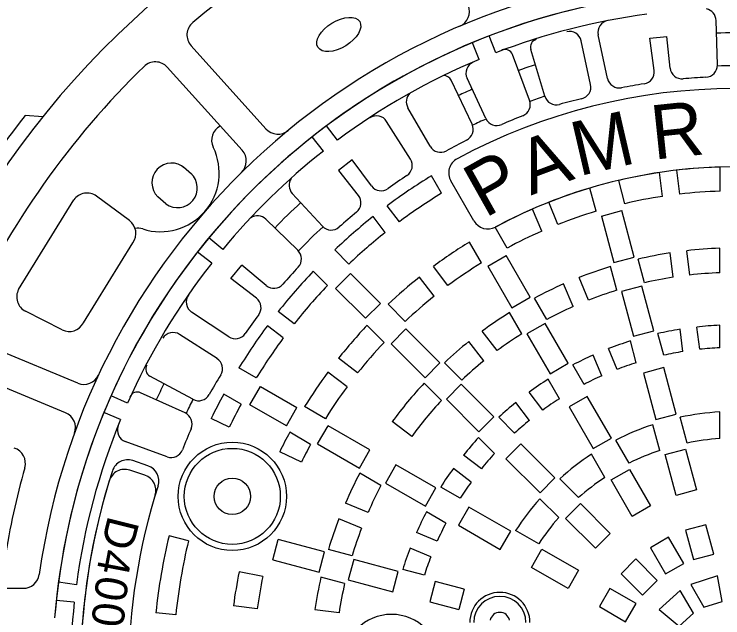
# Model space of a CAD drawing. Extents: x -7.1 to 10, y -5 to 6.
# Drawn here: x -5.508 to -4.588, y 0.793 to 1.576 of the extents above; entities that cross this region are included whole.
import ezdxf

# ---------------------------------------------------------------- set-up
doc = ezdxf.new("R2010")
doc.units = 0
doc.layers.add('Level 1', color=7, linetype='Continuous')

# ---------------------------------------------------------------- blocks, each defined once
blk = doc.blocks.new('CRAN')
at = {"layer": 'Level 1'}
for p, q in [((-3.652, 6.599), (-1.391, 7.083)), ((-3.232, 4.178), (-1.568, 4.4)), ((-1.568, 4.4), (-1.47, 3.52)), ((-3.114, 3.352), (-1.47, 3.52)), ((-2.949, 0.9), (-0.638, 0.965)), ((-2.949, -0.892), (-0.638, -0.957)), ((-3.114, -3.345), (-1.471, -3.52)), ((-1.568, -4.392), (-1.47, -3.512)), ((-3.232, -4.17), (-1.568, -4.392)), ((-3.652, -6.592), (-1.391, -7.076))]:
    blk.add_line(p, q, dxfattribs=at)
for centre, radius, start, end in [((-1.26, 6.472), 0.625, 11.0144, 102.0722), ((-3.521, 5.988), 0.625, 102.0722, 190.9368), ((-34.491, 0.004), 30.918, 8.7409, 10.9368), ((-3.315, 4.797), 0.625, 188.7409, 277.6056), ((-3.048, 2.731), 0.625, 96.0776, 184.9422), ((-34.473, 0.013), 30.918, 2.7463, 4.9422), ((-2.967, 1.524), 0.625, 182.7463, 271.611), ((-0.656, 1.589), 0.625, 271.611, 348.8242), ((-2.967, -1.517), 0.625, 88.389, 177.2537), ((-0.656, -1.582), 0.625, 11.1758, 88.389), ((-34.473, -0.006), 30.918, 355.0578, 357.2537), ((-3.048, -2.723), 0.625, 175.0578, 263.9224), ((-3.315, -4.79), 0.625, 82.3944, 171.2591), ((-34.491, 0.004), 30.918, 349.0632, 351.2591), ((-3.521, -5.981), 0.625, 169.0632, 257.9278), ((-1.26, -6.464), 0.625, 257.9278, 348.9856)]:
    blk.add_arc(centre, radius, start, end, dxfattribs=at)

msp = doc.modelspace()

# ---------------------------------------------------------------- linework, layer by layer
at = {"layer": 'Level 1'}
for p, q in [((-4.59489, 1.51031), (-4.59652, 1.56809)), ((-4.88249, 1.52608), (-4.89092, 1.54795)), ((-4.73738, 1.49275), (-4.74947, 1.54927)), ((-4.68239, 1.54485), (-4.66039, 1.5473)), ((-4.6562, 1.50619), (-4.66058, 1.54728)), ((-4.90382, 1.51753), (-4.91283, 1.53917)), ((-4.75936, 1.48502), (-4.77158, 1.54152)), ((-4.67684, 1.50325), (-4.68239, 1.54485)), ((-5.18073, 1.42741), (-5.27802, 1.53531)), ((-4.81886, 1.4697), (-4.83705, 1.53039)), ((-4.83861, 1.4644), (-4.86087, 1.52372)), ((-5.21167, 1.39951), (-5.30897, 1.50741)), ((-4.91326, 1.43331), (-4.94052, 1.49051)), ((-4.89526, 1.44059), (-4.91972, 1.49296)), ((-4.96766, 1.40474), (-4.99651, 1.45483)), ((-5.47019, 1.44311), (-5.49337, 1.44454)), ((-5.08805, 1.41258), (-5.10206, 1.43136)), ((-5.10628, 1.39859), (-5.12079, 1.417)), ((-5.2774, 1.36875), (-5.28788, 1.3778)), ((-4.666, 1.33974), (-4.67008, 1.37073)), ((-4.64355, 1.34273), (-4.64752, 1.37372)), ((-4.59125, 1.3465), (-4.59118, 1.37776)), ((-4.95299, 1.3438), (-4.96596, 1.36639)), ((-4.91087, 1.30787), (-4.94083, 1.35976)), ((-4.71515, 1.33028), (-4.72295, 1.36055)), ((-4.7523, 1.32035), (-4.76032, 1.35057)), ((-5.50187, 1.21905), (-5.43013, 1.33531)), ((-5.35803, 1.30832), (-5.40074, 1.33998)), ((-5.3107, 1.33021), (-5.32118, 1.33927)), ((-5.00763, 1.30688), (-5.02341, 1.32759)), ((-4.80184, 1.30318), (-4.8137, 1.33209)), ((-4.82275, 1.29449), (-4.83472, 1.32336)), ((-4.7454, 1.31425), (-4.71899, 1.32133)), ((-4.70281, 1.26094), (-4.71899, 1.32133)), ((-4.70281, 1.26094), (-4.71899, 1.32133)), ((-5.02588, 1.29284), (-5.04174, 1.31351)), ((-4.7454, 1.31425), (-4.72922, 1.25386)), ((-4.86778, 1.27262), (-4.88315, 1.29984)), ((-5.4177, 1.17549), (-5.35344, 1.27954)), ((-5.23683, 1.27101), (-5.25489, 1.28595)), ((-4.9011, 1.25342), (-4.91667, 1.28053)), ((-5.07326, 1.25179), (-5.09151, 1.27038)), ((-4.59178, 1.24061), (-4.59178, 1.2724)), ((-5.25124, 1.25311), (-5.26969, 1.26756)), ((-4.89285, 1.24931), (-4.86917, 1.26298)), ((-4.83791, 1.20884), (-4.86917, 1.26298)), ((-4.83791, 1.20884), (-4.86917, 1.26298)), ((-4.72922, 1.25386), (-4.70281, 1.26094)), ((-4.65216, 1.23482), (-4.65631, 1.26633)), ((-4.63048, 1.23772), (-4.63462, 1.26923)), ((-4.68948, 1.22762), (-4.69764, 1.25834)), ((-5.10101, 1.22412), (-5.11939, 1.24259)), ((-4.9445, 1.22401), (-4.96344, 1.24887)), ((-4.89285, 1.24931), (-4.86159, 1.19517)), ((-4.7254, 1.21794), (-4.73363, 1.24865)), ((-5.0903, 1.22025), (-5.07096, 1.23959)), ((-5.07096, 1.23959), (-5.03229, 1.20091)), ((-4.96245, 1.2102), (-4.98148, 1.23499)), ((-4.76204, 1.20513), (-4.7742, 1.23449)), ((-4.78223, 1.19672), (-4.79439, 1.22608)), ((-5.05162, 1.18157), (-5.0903, 1.22025)), ((-4.69269, 1.2232), (-4.7191, 1.21612)), ((-4.7191, 1.21612), (-4.7036, 1.15824)), ((-4.67718, 1.16532), (-4.69269, 1.2232)), ((-4.86159, 1.19517), (-4.83791, 1.20884)), ((-4.81641, 1.1801), (-4.83225, 1.20767)), ((-5.05162, 1.18157), (-5.03229, 1.20091)), ((-5.00028, 1.17743), (-5.02218, 1.19974)), ((-5.44549, 1.1667), (-5.49288, 1.19069)), ((-5.14423, 1.17432), (-5.16484, 1.19025)), ((-4.84861, 1.16146), (-4.86451, 1.18899)), ((-5.15824, 1.15604), (-5.1789, 1.17189)), ((-5.0275, 1.15025), (-5.04956, 1.17241)), ((-4.81837, 1.175), (-4.84205, 1.16133)), ((-4.78841, 1.12311), (-4.81837, 1.175)), ((-4.61779, 1.14132), (-4.62158, 1.17018)), ((-4.59178, 1.14332), (-4.59178, 1.17244)), ((-5.24432, 1.12934), (-5.29292, 1.16064)), ((-5.01847, 1.14842), (-4.99913, 1.16776)), ((-4.95493, 1.12355), (-4.99913, 1.16776)), ((-4.95493, 1.12355), (-4.99913, 1.16776)), ((-4.88068, 1.13961), (-4.90002, 1.16482)), ((-4.84205, 1.16133), (-4.81209, 1.10944)), ((-4.7036, 1.15824), (-4.67718, 1.16532)), ((-4.66449, 1.13361), (-4.67197, 1.16175)), ((-4.63947, 1.13841), (-4.64327, 1.16727)), ((-5.425, 1.09741), (-5.55924, 1.15302)), ((-4.89801, 1.12625), (-4.91735, 1.15146)), ((-4.70022, 1.12396), (-4.70776, 1.1521)), ((-5.01847, 1.14842), (-4.97426, 1.10421)), ((-4.72483, 1.1153), (-4.73597, 1.14219)), ((-4.74502, 1.10688), (-4.75616, 1.13377)), ((-5.06181, 1.11061), (-5.08654, 1.12972)), ((-4.97426, 1.10421), (-4.95493, 1.12355)), ((-4.92672, 1.10136), (-4.94915, 1.12388)), ((-4.81209, 1.10944), (-4.78841, 1.12311)), ((-5.44094, 1.05892), (-5.57519, 1.11453)), ((-5.19338, 1.10412), (-5.21581, 1.11735)), ((-4.76795, 1.09576), (-4.78246, 1.12101)), ((-4.66437, 1.1175), (-4.69078, 1.11042)), ((-4.64818, 1.05709), (-4.66437, 1.1175)), ((-5.27556, 1.07643), (-5.33134, 1.10649)), ((-5.07558, 1.09263), (-5.10038, 1.11165)), ((-4.69078, 1.11042), (-4.6746, 1.05001)), ((-4.953, 1.07501), (-4.97548, 1.09749)), ((-4.9273, 1.09592), (-4.94663, 1.07658)), ((-4.88493, 1.05355), (-4.9273, 1.09592)), ((-4.79996, 1.0772), (-4.81453, 1.10242)), ((-5.20167, 1.06925), (-5.188, 1.09293)), ((-5.188, 1.09293), (-5.14063, 1.06558)), ((-4.82149, 1.06246), (-4.83921, 1.08556)), ((-5.36042, 1.0713), (-5.38185, 1.08081)), ((-5.28578, 1.05871), (-5.34347, 1.08492)), ((-5.21302, 1.07021), (-5.23555, 1.0833)), ((-4.94663, 1.07658), (-4.90426, 1.03421)), ((-4.76366, 1.08024), (-4.78734, 1.06656)), ((-4.73239, 1.02607), (-4.76366, 1.08024)), ((-5.1543, 1.0419), (-5.20167, 1.06925)), ((-5.10364, 1.05118), (-5.13056, 1.06706)), ((-4.83881, 1.0491), (-4.85653, 1.0722)), ((-5.36946, 1.05017), (-5.39113, 1.0591)), ((-5.1543, 1.0419), (-5.14063, 1.06558)), ((-4.78734, 1.06656), (-4.75607, 1.0124)), ((-4.59178, 1.02541), (-4.59178, 1.06001)), ((-5.22843, 1.04026), (-5.25185, 1.05164)), ((-4.90426, 1.03421), (-4.88493, 1.05355)), ((-4.85808, 1.03243), (-4.87863, 1.05307)), ((-4.6746, 1.05001), (-4.64818, 1.05709)), ((-4.63422, 1.01969), (-4.6431, 1.05312)), ((-5.1137, 1.01846), (-5.10002, 1.04214)), ((-5.04588, 1.01088), (-5.10002, 1.04214)), ((-5.04588, 1.01088), (-5.10002, 1.04214)), ((-4.9916, 1.02822), (-5.01681, 1.04757)), ((-4.6697, 1.01007), (-4.67866, 1.04349)), ((-5.12289, 1.01789), (-5.14993, 1.03359)), ((-5.309, 1.00182), (-5.36332, 1.02156)), ((-4.8842, 1.00621), (-4.9048, 1.02681)), ((-4.75607, 1.0124), (-4.73239, 1.02607)), ((-4.70923, 0.99357), (-4.72646, 1.02355)), ((-5.1137, 1.01846), (-5.05955, 0.9872)), ((-4.84992, 1.01854), (-4.86926, 0.99921)), ((-4.8057, 0.97432), (-4.84992, 1.01854)), ((-5.13472, 0.99477), (-5.16283, 1.00841)), ((-5.05955, 0.9872), (-5.04588, 1.01088)), ((-4.90118, 0.98641), (-4.92427, 1.00413)), ((-4.74101, 0.97509), (-4.75831, 1.00505)), ((-4.66245, 1.00469), (-4.63604, 1.01177)), ((-4.64828, 0.9518), (-4.66245, 1.00469)), ((-4.63604, 1.01177), (-4.62187, 0.95888)), ((-5.3339, 0.99027), (-5.35366, 0.99688)), ((-4.86926, 0.99921), (-4.82503, 0.95499)), ((-5.33781, 0.97785), (-5.35757, 0.98446)), ((-5.01204, 0.99134), (-5.02571, 0.96766)), ((-4.96015, 0.96138), (-5.01204, 0.99134)), ((-4.91445, 0.96902), (-4.93755, 0.98674)), ((-4.73261, 0.97177), (-4.70893, 0.98544)), ((-4.70893, 0.98544), (-4.68155, 0.93802)), ((-5.03146, 0.96449), (-5.05899, 0.98039)), ((-5.02571, 0.96766), (-4.97382, 0.9377)), ((-4.82503, 0.95499), (-4.8057, 0.97432)), ((-4.77491, 0.94892), (-4.79931, 0.97342)), ((-4.70523, 0.92435), (-4.73261, 0.97177)), ((-4.97382, 0.9377), (-4.96015, 0.96138)), ((-4.92875, 0.94793), (-4.95394, 0.96254)), ((-4.62187, 0.95888), (-4.64828, 0.9518)), ((-5.0483, 0.92953), (-5.07766, 0.94169)), ((-4.80083, 0.92284), (-4.82529, 0.94731)), ((-4.79186, 0.92181), (-4.77252, 0.94114)), ((-4.77252, 0.94114), (-4.7338, 0.90242)), ((-4.9472, 0.91585), (-4.97242, 0.93041)), ((-4.91728, 0.93663), (-4.93095, 0.91295)), ((-4.86312, 0.90536), (-4.91728, 0.93663)), ((-4.68155, 0.93802), (-4.70523, 0.92435)), ((-5.05663, 0.90931), (-5.08599, 0.92147)), ((-4.75314, 0.88309), (-4.79186, 0.92181)), ((-4.93095, 0.91295), (-4.87679, 0.88168)), ((-4.60971, 0.91351), (-4.63612, 0.90643)), ((-4.59957, 0.87566), (-4.60971, 0.91351)), ((-4.95847, 0.89232), (-4.98536, 0.90346)), ((-4.87679, 0.88168), (-4.86312, 0.90536)), ((-4.8268, 0.88879), (-4.85672, 0.90614)), ((-4.7338, 0.90242), (-4.75314, 0.88309)), ((-4.63612, 0.90643), (-4.62598, 0.86859)), ((-5.28138, 0.89256), (-5.30652, 0.89937)), ((-5.17204, 0.86827), (-5.16496, 0.89468)), ((-5.10458, 0.8785), (-5.16496, 0.89468)), ((-5.10458, 0.8785), (-5.16496, 0.89468)), ((-4.65807, 0.89734), (-4.68175, 0.88367)), ((-4.63848, 0.86341), (-4.65807, 0.89734)), ((-4.96679, 0.87209), (-4.99369, 0.88323)), ((-4.68175, 0.88367), (-4.66216, 0.84974)), ((-5.11165, 0.85209), (-5.10458, 0.8785)), ((-5.06905, 0.87339), (-5.09974, 0.88168)), ((-4.83616, 0.85822), (-4.82248, 0.8819)), ((-4.82248, 0.8819), (-4.77506, 0.85452)), ((-4.62598, 0.86859), (-4.59957, 0.87566)), ((-5.17204, 0.86827), (-5.11165, 0.85209)), ((-5.06683, 0.86839), (-5.07391, 0.84198)), ((-5.00896, 0.85288), (-5.06683, 0.86839)), ((-4.70059, 0.86921), (-4.71993, 0.84988)), ((-4.67289, 0.84151), (-4.70059, 0.86921)), ((-4.97515, 0.84802), (-5.00326, 0.85561)), ((-4.78873, 0.83084), (-4.83616, 0.85822)), ((-4.66216, 0.84974), (-4.63848, 0.86341)), ((-5.18496, 0.84632), (-5.21558, 0.85255)), ((-5.01603, 0.82647), (-5.00896, 0.85288)), ((-4.77506, 0.85452), (-4.78873, 0.83084)), ((-4.71993, 0.84988), (-4.69222, 0.82217)), ((-4.59461, 0.84745), (-4.62941, 0.83598)), ((-4.58874, 0.81411), (-4.59461, 0.84745)), ((-5.42689, 0.83586), (-5.45012, 0.83896)), ((-5.07864, 0.83743), (-5.10935, 0.84566)), ((-5.07391, 0.84198), (-5.01603, 0.82647)), ((-4.96114, 0.84007), (-4.96821, 0.81366)), ((-4.92341, 0.82996), (-4.96114, 0.84007)), ((-4.69222, 0.82217), (-4.67289, 0.84151)), ((-5.56204, 0.83118), (-5.49564, 0.83118)), ((-4.92341, 0.82996), (-4.93048, 0.80355)), ((-4.73439, 0.83103), (-4.74806, 0.80735)), ((-4.70045, 0.81144), (-4.73439, 0.83103)), ((-4.64294, 0.82817), (-4.67027, 0.80377)), ((-4.62597, 0.79878), (-4.64294, 0.82817)), ((-4.62941, 0.83598), (-4.61244, 0.80659)), ((-5.42962, 0.81305), (-5.45293, 0.81553)), ((-4.96821, 0.81366), (-4.93048, 0.80355)), ((-4.71412, 0.78776), (-4.70045, 0.81144)), ((-4.61244, 0.80659), (-4.58874, 0.81411)), ((-5.192, 0.80441), (-5.22298, 0.80854)), ((-5.08586, 0.7993), (-5.11737, 0.80345)), ((-4.74806, 0.80735), (-4.71412, 0.78776)), ((-4.67027, 0.80377), (-4.64433, 0.78201)), ((-5.29779, 0.79681), (-5.32369, 0.79949)), ((-4.64433, 0.78201), (-4.62597, 0.79878))]:
    msp.add_line(p, q, dxfattribs=at)
for radius in [0.07031, 0.06231, 0.02369]:
    msp.add_circle((-5.22444, 0.95048), radius, dxfattribs=at)
for centre, radius, start, end in [((-4.57265, 0.72181), 1.15162, 195.07169, 189.12267), ((-4.5725, 0.7217), 1.09834, 112.86457, 129.82243), ((-4.57249, 0.72178), 0.91146, 12.31851, 171.9696), ((-4.57249, 0.72178), 0.88542, 5.66744, 175.39465), ((-4.57249, 0.72178), 0.88542, 5.66744, 126.73442), ((-4.93742, 1.57968), 0.02083, 293.04383, 21.72806), ((-4.61214, 1.56765), 0.01563, 1.61098, 78.82418), ((-4.57249, 0.72178), 0.86198, 97.60558, 111.07801), ((-5.26255, 1.54926), 0.02083, 129.82243, 222.04), ((-4.73419, 1.55254), 0.01563, 101.01435, 192.07218), ((-4.78686, 1.53821), 0.01562, 12.21206, 103.26989), ((-4.57249, 0.72178), 0.83011, 88.3735, 91.6265), ((-4.82707, 1.53338), 0.01042, 105.96915, 196.67866), ((-4.87063, 1.52006), 0.01042, 20.56861, 111.27812), ((-4.57249, 0.72178), 0.88542, 114.66149, 175.39465), ((-4.57249, 0.7217), 1.09834, 134.21887, 155.28148), ((-5.32444, 1.49346), 0.02083, 42.04, 134.25473), ((-4.57249, 0.72178), 0.86198, 112.60558, 126.73442), ((-4.90556, 1.49957), 0.01562, 113.97738, 205.03521), ((-4.57249, 0.72178), 0.83011, 108.15242, 109.7577), ((-4.61051, 1.50987), 0.01563, 272.74634, 1.61098), ((-4.57249, 0.72178), 0.78745, 88.36809, 91.63191), ((-4.69233, 1.50118), 0.01563, 278.74094, 7.60558), ((-4.64066, 1.50785), 0.01563, 186.07758, 274.94222), ((-4.94992, 1.48603), 0.01042, 25.47558, 93.37664), ((-4.7221, 1.49602), 0.01563, 192.07218, 280.93682), ((-4.57273, 0.72221), 0.77294, 92.74634, 94.94222), ((-4.77463, 1.48172), 0.01562, 283.34742, 12.21206), ((-4.57249, 0.72178), 0.77294, 98.74094, 100.93682), ((-4.98297, 1.46263), 0.01562, 135.24421, 209.94218), ((-4.57249, 0.72178), 0.75781, 61.61988, 118.38012), ((-4.57249, 0.72178), 0.83011, 114.22478, 115.58518), ((-4.85324, 1.45891), 0.01562, 291.70397, 20.56861), ((-4.57249, 0.72178), 0.78745, 108.23227, 109.71842), ((-4.80389, 1.47418), 0.01562, 196.67866, 285.5433), ((-4.59259, 0.71446), 0.77294, 103.34742, 105.5433), ((-4.57312, 0.72157), 1.17028, 141.8462, 151.62506), ((-4.56162, 0.72625), 0.77294, 111.70397, 113.89985), ((-4.57249, 0.72178), 0.78745, 114.1803, 115.59091), ((-4.8811, 1.4472), 0.01562, 205.03521, 293.89985), ((-5.23051, 1.41257), 0.02083, 117.45124, 206.08424), ((-5.16525, 1.44136), 0.02083, 222.04, 309.48029), ((-4.92737, 1.42659), 0.01562, 296.61094, 25.47558), ((-4.57415, 0.72156), 0.77294, 116.61094, 118.80682), ((-5.31757, 1.36995), 0.0761, 252.33436, 26.08424), ((-4.57249, 0.72178), 0.86198, 128.26199, 140.41801), ((-5.22714, 1.38555), 0.02083, 314.60341, 42.04), ((-4.95412, 1.41254), 0.01562, 209.94218, 298.80682), ((-5.30323, 1.35741), 0.02552, 48.43946, 225.3147), ((-4.92279, 1.37018), 0.02083, 118.38012, 210), ((-4.57249, 0.72178), 0.65625, 61.76323, 118.23677), ((-4.57249, 0.72178), 0.65625, 98.55203, 103.25436), ((-4.57249, 0.72178), 0.65625, 91.63169, 96.56459), ((-5.29535, 1.3506), 0.02552, 233.02789, 48.43175), ((-4.57249, 0.72178), 0.75521, 121.39947, 126.6608), ((-5.41315, 1.32324), 0.02083, 53.4552, 144.60971), ((-4.57249, 0.72178), 0.72917, 121.45447, 126.63801), ((-4.57249, 0.72178), 0.65625, 106.63169, 111.56459), ((-4.57249, 0.72178), 0.625, 91.72031, 96.52788), ((-4.57249, 0.72178), 0.625, 98.60431, 103.19389), ((-4.57249, 0.72178), 0.83011, 132.7192, 135.97333), ((-4.57249, 0.72178), 0.65625, 113.55203, 118.25436), ((-4.57249, 0.72178), 0.625, 106.72031, 111.52788), ((-5.37044, 1.29159), 0.02083, 324.66383, 53.4552), ((-4.57249, 0.72178), 0.75521, 128.41505, 133.41284), ((-4.89283, 1.31829), 0.02083, 210, 298.23677), ((-5.34698, 1.27759), 0.02083, 72.33436, 100.12489), ((-4.57249, 0.72178), 0.78745, 132.71581, 135.97743), ((-4.57249, 0.72178), 0.72917, 128.44749, 133.3753), ((-4.57249, 0.72178), 0.625, 113.60431, 118.19389), ((-4.57249, 0.72178), 0.65625, 121.63169, 126.56459), ((-4.57249, 0.72178), 0.55096, 92.00587, 96.47515), ((-4.57249, 0.72178), 0.55096, 98.75013, 103.12895), ((-4.57249, 0.72178), 0.86198, 141.94558, 156.07801), ((-4.57249, 0.72178), 0.625, 121.72031, 126.52788), ((-4.57249, 0.72178), 0.75521, 136.39947, 141.6608), ((-4.57249, 0.72178), 0.55096, 107.00587, 111.47515), ((-4.57249, 0.72178), 0.65625, 128.55203, 133.25436), ((-4.57249, 0.72178), 0.51919, 98.82664, 103.02167), ((-4.57249, 0.72178), 0.51919, 92.12867, 96.41243), ((-4.57249, 0.72178), 0.72917, 136.45447, 141.63801), ((-4.57249, 0.72178), 0.55096, 113.75013, 118.12895), ((-5.48347, 1.20928), 0.02083, 152.03534, 243.1452), ((-4.57249, 0.72178), 0.51919, 107.12867, 111.41243), ((-4.57249, 0.72178), 0.625, 128.60431, 133.19389), ((-4.57249, 0.72178), 0.51919, 113.82664, 118.02167), ((-4.57249, 0.72178), 0.55096, 122.00587, 126.47515), ((-5.43608, 1.18529), 0.02083, 243.1452, 331.94061), ((-4.57249, 0.72178), 0.75521, 143.41505, 148.41284), ((-4.57249, 0.72178), 0.65625, 136.63169, 141.56459), ((-4.57249, 0.72178), 0.45108, 92.45028, 96.24818), ((-5.30138, 1.14751), 0.01562, 57.21206, 148.26989), ((-4.57249, 0.72178), 0.51919, 122.12867, 126.41243), ((-4.57249, 0.72178), 0.45108, 99.02701, 102.74069), ((-4.57249, 0.72178), 0.72917, 143.44749, 148.3753), ((-4.57249, 0.72178), 0.625, 136.72031, 141.52788), ((-4.57249, 0.72178), 0.55096, 128.75013, 133.12895), ((-4.57249, 0.72178), 0.45108, 107.45028, 111.24818), ((-4.57249, 0.72178), 0.42198, 92.61937, 96.16184), ((-4.57249, 0.72178), 0.45108, 114.02701, 117.74069), ((-4.57249, 0.72178), 0.42198, 99.13234, 102.59298), ((-5.25278, 1.1162), 0.01562, 328.34742, 57.21206), ((-4.57249, 0.72178), 0.51919, 128.82664, 133.02167), ((-4.57249, 0.72178), 0.42198, 107.61937, 111.16184), ((-5.3264, 1.11566), 0.01042, 150.96915, 241.67866), ((-5.41702, 1.11666), 0.02083, 247.5, 334.94038), ((-4.58152, 0.70239), 0.77294, 148.34742, 150.5433), ((-4.57249, 0.72178), 0.65625, 143.55203, 148.25436), ((-4.57249, 0.72178), 0.42198, 114.13234, 117.59298), ((-4.57249, 0.72178), 0.83011, 153.15242, 154.7577), ((-4.57249, 0.72178), 0.55096, 137.00587, 143.75013), ((-4.57249, 0.72178), 0.45108, 122.45028, 126.24818), ((-5.34778, 1.07544), 0.01042, 65.56861, 156.27812), ((-4.57249, 0.72178), 0.625, 143.60431, 148.19389), ((-4.57249, 0.72178), 0.78745, 153.23227, 154.71842), ((-5.26815, 1.09018), 0.01562, 241.67866, 330.5433), ((-4.57249, 0.72178), 0.75521, 151.39947, 154.10132), ((-4.57249, 0.72178), 0.42198, 122.61937, 126.16184), ((-4.57249, 0.72178), 0.72917, 151.45447, 154.10132), ((-4.57249, 0.72178), 0.51919, 137.12867, 143.82664), ((-4.57249, 0.72178), 0.45108, 129.02701, 132.74069), ((-5.44891, 1.03967), 0.02083, 340.06349, 67.5), ((-5.29224, 1.04449), 0.01562, 336.70397, 65.56861), ((-4.57249, 0.72178), 0.33878, 93.26326, 102.03051), ((-4.57249, 0.72178), 0.86198, 157.60558, 172.39442), ((-4.57249, 0.72178), 0.42198, 129.13234, 132.59298), ((-5.35799, 1.03624), 0.01562, 158.97738, 250.03521), ((-4.57249, 0.72178), 0.33878, 108.26326, 117.03051), ((-4.56797, 0.73263), 0.77294, 156.70397, 158.89985), ((-4.57249, 0.72178), 0.65625, 151.63169, 154.10132), ((-4.57249, 0.72178), 0.45108, 137.45028, 141.24818), ((-4.57249, 0.72178), 0.30425, 93.63416, 101.70655), ((-5.5138, 0.99333), 0.02083, 344.02549, 72.65547), ((-4.57249, 0.72178), 0.625, 151.72031, 154.10132), ((-5.30366, 1.01651), 0.01562, 250.03521, 338.89985), ((-4.57249, 0.72178), 0.42198, 137.61937, 141.16184), ((-4.57249, 0.72178), 0.33878, 123.26326, 132.03051), ((-4.57249, 0.72178), 0.30425, 108.63416, 116.70655), ((-5.36027, 0.97712), 0.02083, 71.5, 162.04053), ((-4.56744, 0.72242), 0.96354, 164.02549, 171.20989), ((-5.36418, 0.96471), 0.02083, 71.5, 162.94156), ((-5.34051, 0.97051), 0.02083, 342.05448, 71.5), ((-4.57249, 0.72178), 0.45108, 144.02701, 147.74069), ((-4.57249, 0.72178), 0.84896, 162.04053, 197.95947), ((-5.34442, 0.95809), 0.02083, 342.97876, 71.5), ((-4.57249, 0.72178), 0.55096, 152.00587, 156.47515), ((-4.57249, 0.72178), 0.30425, 123.63416, 131.70655), ((-4.57249, 0.72178), 0.84896, 162.94156, 197.05844), ((-4.57249, 0.72178), 0.42198, 144.13234, 147.59298), ((-4.57249, 0.72178), 0.78646, 162.05448, 197.94552), ((-4.57249, 0.72178), 0.51919, 152.12867, 156.41243), ((-4.57249, 0.72178), 0.33878, 138.26326, 147.03051), ((-4.57249, 0.72178), 0.45108, 152.45028, 156.24818), ((-4.57249, 0.72178), 0.55096, 158.75013, 163.12895), ((-4.57249, 0.72178), 0.30425, 138.63416, 146.70655), ((-4.57249, 0.72178), 0.42198, 152.61937, 156.16184), ((-4.57249, 0.72178), 0.51919, 158.82664, 163.02167), ((-4.57249, 0.72178), 0.75521, 166.39947, 174.09372), ((-4.57249, 0.72178), 0.72917, 166.45447, 174.09372), ((-4.57249, 0.72178), 0.45108, 159.02701, 162.74069), ((-4.57249, 0.72178), 0.42198, 159.13234, 162.59298), ((-5.49564, 0.85202), 0.02083, 270, 351.9696), ((-4.57249, 0.72178), 0.65625, 168.5057, 172.40235), ((-4.57249, 0.72178), 0.625, 168.5057, 172.40235), ((-4.57249, 0.72178), 0.55096, 167.00587, 171.47515), ((-4.57249, 0.72178), 0.51919, 167.12867, 171.41243), ((-4.87718, 0.78688), 0.03906, 0, 180), ((-4.87718, 0.78688), 0.03385, 0, 180), ((-4.57249, 0.72178), 0.86198, 173.92199, 186.07801), ((-5.0178, 0.7348), 0.0625, 0, 180), ((-4.87718, 0.78688), 0.01302, 13.17501, 166.82499)]:
    msp.add_arc(centre, radius, start, end, dxfattribs=at)
msp.add_ellipse((-5.08621, 1.54984), major_axis=(-0.0271, -0.01662), ratio=0.540989, dxfattribs=at)

# ---------------------------------------------------------------- block references
at = {"layer": 'Level 1', "xscale": 0.024999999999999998, "yscale": 0.024999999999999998, "rotation": 134.33999999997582}
msp.add_blockref('CRAN', (-5.17494, 1.33826), dxfattribs=at)

# ---------------------------------------------------------------- texts
at = {"layer": 'Level 1'}
for s, height, rotation, p in [('R', 0.07031, 6.01703, (-4.67738, 1.38731)), ('M', 0.07031, 13.04348, (-4.7748, 1.36574)), ('A', 0.07031, 20.63071, (-4.83702, 1.34075)), ('P', 0.07031, 29.31, (-4.89668, 1.31089)), ('D', 0.04167, 256.03, (-5.38529, 0.92667)), ('4', 0.04167, 259.13, (-5.3948, 0.88382)), ('0', 0.04167, 260.07128, (-5.39936, 0.84938)), ('0', 0.04167, 263.15837, (-5.40403, 0.81488))]:
    msp.add_text(s, height=height, rotation=rotation, dxfattribs=at).set_placement(p)

doc.saveas('drawing.dxf')
